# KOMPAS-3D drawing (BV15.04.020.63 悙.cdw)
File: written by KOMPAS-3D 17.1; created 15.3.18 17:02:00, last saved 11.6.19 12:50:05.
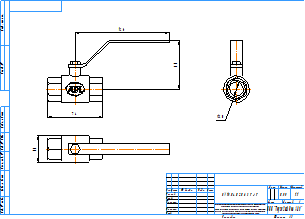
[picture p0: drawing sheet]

Sheet 1: A3, landscape

Title block, sheet 1: name: BV15.04.020.63 Р/Р; material: Внимание! Данный продукт является объектом авторского права ООО «Торговый Дом АДЛ». / Запрещается изменение, копирование, распространение / (в том числе путем копирования на другие сайты и ресурсы в Интернете) / или любое иное использование информации и объектов без предварительного / согласия правообладателя (ООО «Торговый Дом АДЛ»).; mass: 0,55; sheets: 1; organisation: ООО "Торговый дом АДЛ"; sheet format: A3; stored path: \\adlc.lan\data\АДЛ_ПКД\3D-модели\ADL production\Краны шаровые серии BV\BV15\KOMPAS 2D\BV15.04.020.63 РР.cdw

Views: Вид 1, Проекционный вид 2, Проекционный вид 3
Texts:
  kka
  adl
Dimensions and other numbers on the sheet: 74; 126; 65; 20; 36; 1:1; 1; 0,55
